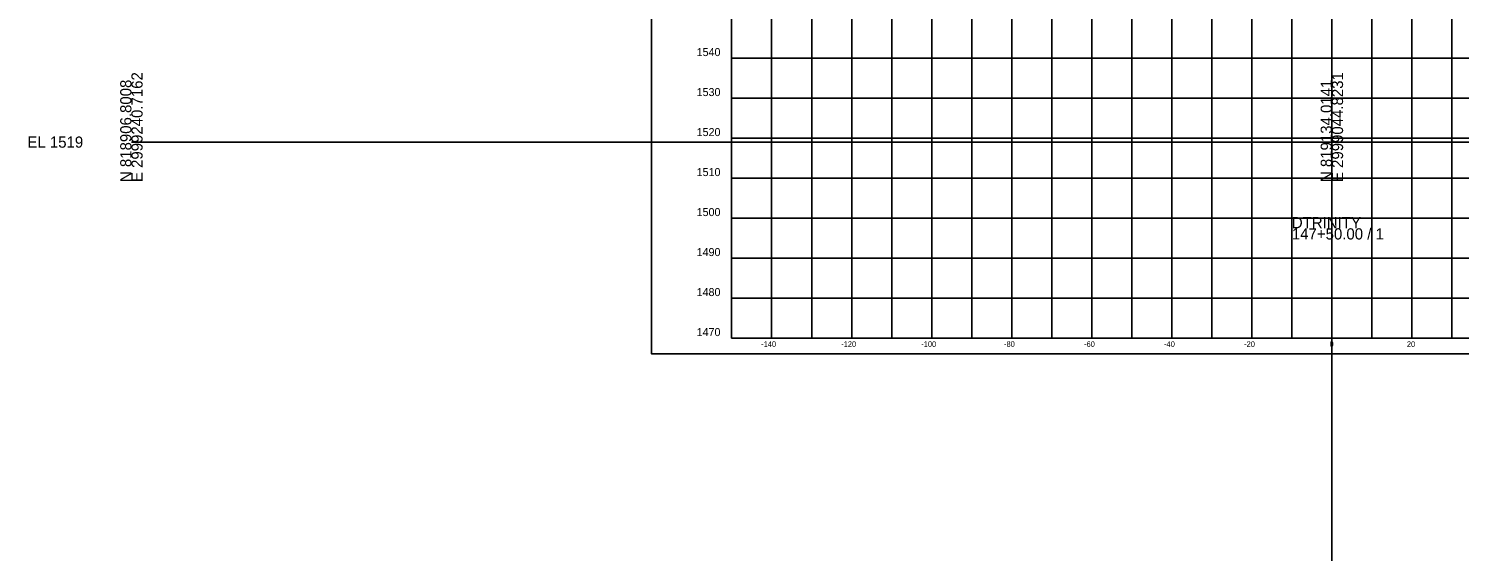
# Model space of a CAD drawing. Extents: x -26 to 603, y -10 to 4805.
# Drawn here: x -25.7 to 331.9, y 2397.7 to 2528.4 of the extents above; entities that cross this region are included whole.
import ezdxf

# ---------------------------------------------------------------- set-up
doc = ezdxf.new("R2010")
doc.units = 0
for name, color, linetype in [('DESIGN - SHEET - Corner Text', 7, 'Continuous'), ('DESIGN - SHEET - Light Grid', 7, 'Continuous'), ('DESIGN - SHEET - Linework', 7, 'Continuous'), ('DESIGN - SHEET - Plot Shape', 7, 'Continuous')]:
    doc.layers.add(name, color=color, linetype=linetype)

msp = doc.modelspace()

# ---------------------------------------------------------------- linework, layer by layer
at = {"layer": 'DESIGN - SHEET - Light Grid'}
for p, q in [((300, 2500), (300, 2963.55)), ((0, 2500), (300, 2500)), ((300, 2500), (600, 2500)), ((300, 2000), (300, 2478.45))]:
    msp.add_line(p, q, dxfattribs=at)
at = {"layer": 'DESIGN - SHEET - Linework'}
for p, q in [((160, 2451), (160, 2661)), ((170, 2451), (170, 2661)), ((180, 2451), (180, 2661)), ((190, 2451), (190, 2661)), ((200, 2451), (200, 2661)), ((210, 2451), (210, 2661)), ((220, 2451), (220, 2661)), ((230, 2451), (230, 2661)), ((240, 2451), (240, 2661)), ((250, 2451), (250, 2661)), ((260, 2451), (260, 2661)), ((270, 2451), (270, 2661)), ((280, 2451), (280, 2661)), ((290, 2451), (290, 2661)), ((300, 2451), (300, 2661)), ((310, 2451), (310, 2661)), ((320, 2451), (320, 2661)), ((330, 2451), (330, 2661)), ((150, 2521), (450, 2521)), ((150, 2511), (450, 2511)), ((150, 2501), (450, 2501)), ((150, 2491), (450, 2491)), ((150, 2481), (450, 2481)), ((150, 2471), (450, 2471)), ((150, 2461), (450, 2461))]:
    msp.add_line(p, q, dxfattribs=at)
msp.add_lwpolyline([(150, 2661), (150, 2451), (450, 2451), (450, 2661)], dxfattribs=at)
at = {"layer": 'DESIGN - SHEET - Plot Shape'}
msp.add_lwpolyline([(130, 2664.94), (470, 2664.94), (470, 2447.06), (130, 2447.06)], close=True, dxfattribs=at)

# ---------------------------------------------------------------- texts
at = {"layer": 'DESIGN - SHEET - Corner Text'}
for s, height, p in [('1540', 2, (141.25, 2521.5)), ('1530', 2, (141.25, 2511.5)), ('1520', 2, (141.25, 2501.5)), ('1510', 2, (141.25, 2491.5)), ('1500', 2, (141.25, 2481.5)), ('1490', 2, (141.25, 2471.5)), ('1480', 2, (141.25, 2461.5)), ('1470', 2, (141.25, 2451.5)), ('-140', 1.4, (157.37, 2448.8)), ('-120', 1.4, (177.37, 2448.8)), ('-100', 1.4, (197.37, 2448.8)), ('-80', 1.4, (218.06, 2448.8)), ('-60', 1.4, (238.06, 2448.8)), ('-40', 1.4, (258.06, 2448.8)), ('-20', 1.4, (278.06, 2448.8)), ('0', 1.4, (299.42, 2448.8)), ('20', 1.4, (318.74, 2448.8))]:
    msp.add_text(s, height=height, dxfattribs=at).set_placement(p)
at = {"layer": 'DESIGN - SHEET - Light Grid'}
for s, p in [('E 2999240.7162', (2.8, 2490)), ('E 2999044.8231', (302.8, 2490)), ('N 818906.8008', (0, 2490)), ('N 819134.0141', (300, 2490))]:
    msp.add_text(s, height=2.8, rotation=90, dxfattribs=at).set_placement(p)
for s, p in [('EL 1519', (-26, 2498.6)), ('147+50.00 / 1', (290, 2475.65)), ('DTRINITY', (290, 2478.45))]:
    msp.add_text(s, height=2.8, dxfattribs=at).set_placement(p)

doc.saveas('drawing.dxf')
